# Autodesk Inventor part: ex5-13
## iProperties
Created: 2006-03
Part Number: ex5-13
Document SubType Name: Modeling
Designer: Elise Moss
Author: Elise Moss
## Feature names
1. Loft1
2. Shell1
3. Extrusion1
4. Sweep1
5. Fillet1
6. Fillet2
